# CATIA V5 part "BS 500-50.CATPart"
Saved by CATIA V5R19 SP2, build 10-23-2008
Part number: BS 500-50
Bounding box of the stored display mesh (mm): x -18.951 to 18.951, y -18.952 to 18.952, z 0 to 130
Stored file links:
  C:\Users\Bora\Desktop\3D Katı model\BS serisi\BS 500\BS 500-50.CATPart
  C:\Program Files\Dassault Systemes\B19\intel_a\reffiles\standard\MetricThickPitch.txt
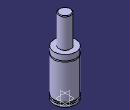
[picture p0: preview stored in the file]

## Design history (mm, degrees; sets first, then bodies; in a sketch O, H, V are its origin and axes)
Body1 (main body)
  Sketch1 on yz-plane, origin (0, 0, 0), H (0, 1, 0), V (0, 0, 1)
    point P1 (10, 129)
    point P3 (10, 129)
    point P5 (19, 69.5)
    point P6 (19, 67.5)
    point P9 (19, 69.5)
    point P14 (19, 67.5)
    line L1 (10, 129) -> (10, 79)
    arc A1 centre (9, 129) radius 1 from (10, 129) to (9, 130) ccw
    arc A2 centre (19, 68.5) radius 1 from (19, 69.5) to (19, 67.5) ccw
    line L2 (19, 0) -> (19, 4)
    line L3 (19, 69.5) -> (19, 79)
    line L4 (17, 7.5) -> (17, 4)
    line L5 (19, 7.5) -> (19, 67.5)
    line L6 (9, 130) -> (0, 130)
    point P15 (0, 130)
    line L7 (10, 79) -> (19, 79)
    line L8 (17, 7.5) -> (19, 7.5)
    line L9 (17, 4) -> (19, 4)
    line L10 (0, 0) -> (19, 0)
    coincidence: P15 V, P1 P3, P5 P9, P6 P14
    tangency: L6 A1
    horizontal: L7 H, L8 H, L9 H, L10 H
  Shaft1: profile Sketch1, axis Sketch1.V, angle 360
  Sketch2 on face of Shaft1 from Sketch1.L10, origin (0, 0, 0), H (1, 0, 0), V (0, -1, 0)
    point P1 (0, 0)
  Hole1: placed by Sketch2, at (0, 0, 0) direction (0, 0, 1), diameter 6.647, depth 4, threaded "M8", thread diameter 8, thread depth 4, pitch 1.25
